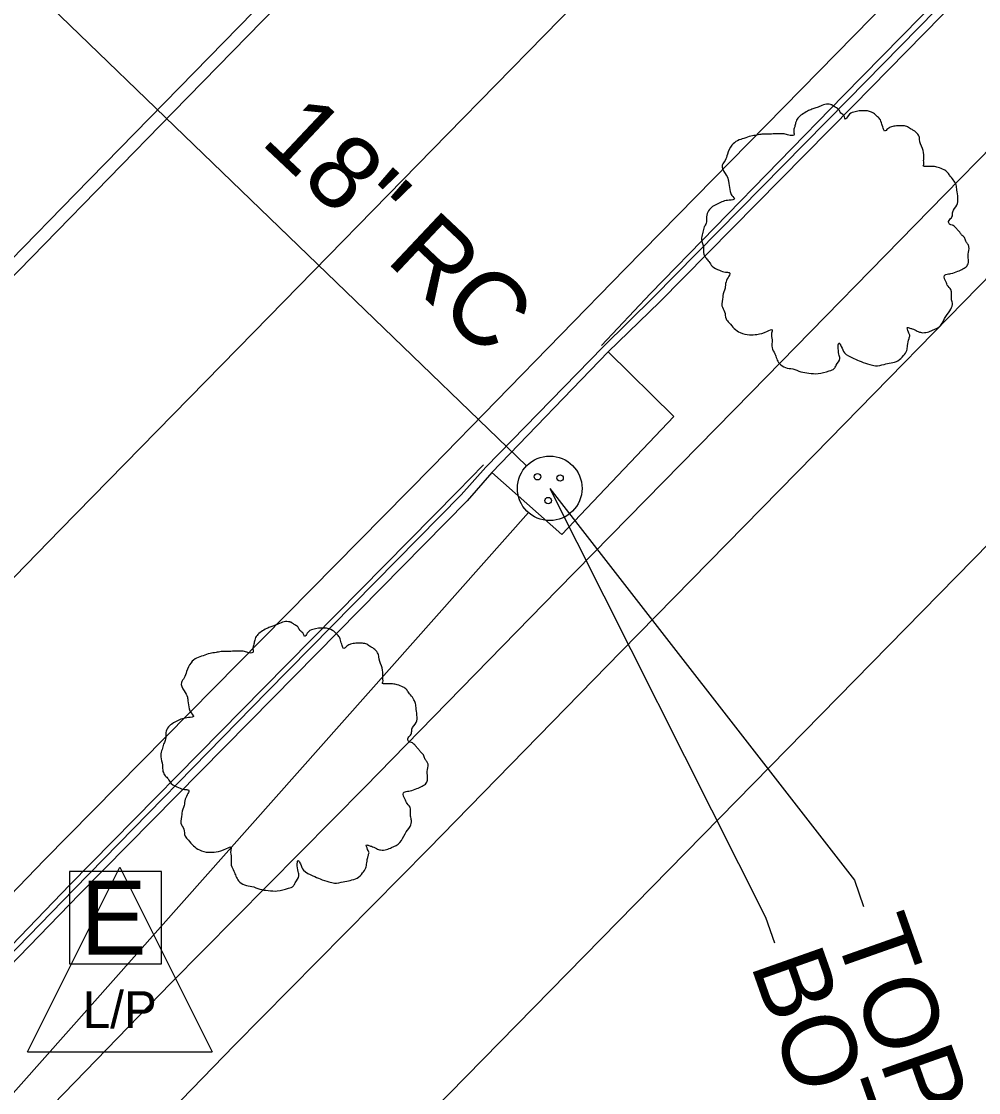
# Model space of a CAD drawing. Extents: x 2004847 to 2009016, y 1134161 to 1140101.
# Drawn here: x 2008246.9 to 2008298.8, y 1139479.2 to 1139537.2 of the extents above; entities that cross this region are included whole.
import ezdxf

# ---------------------------------------------------------------- set-up
doc = ezdxf.new("R2010")
doc.units = 0
for name, color, linetype in [('RD_EX_Conc', 7, 'Continuous'), ('RD_EX_Curb', 7, 'Continuous'), ('RD_EX_DR_Inlet', 7, 'Continuous'), ('RD_EX_DR_Inlet_txCode', 7, 'Continuous'), ('RD_EX_DR_Pipe', 7, 'Continuous'), ('RD_EX_DR_Pipe_txCode', 7, 'Continuous'), ('RD_EX_Pavement_Markings', 7, 'Continuous'), ('RD_EX_Road', 7, 'Continuous'), ('RD_EX_SU_Elec', 7, 'Continuous'), ('RD_EX_UT', 7, 'Continuous'), ('RD_EX_VEG', 7, 'Continuous')]:
    doc.layers.add(name, color=color, linetype=linetype)

msp = doc.modelspace()

# ---------------------------------------------------------------- linework, layer by layer
at = {"layer": 'RD_EX_Conc'}
for points in [[(2008321.411, 1139545.804), (2008310.877, 1139535.196), (2008300.368, 1139524.489), (2008289.885, 1139513.771), (2008279.393, 1139503.086), (2008268.931, 1139492.374), (2008258.431, 1139481.764), (2008248.004, 1139471.024), (2008237.636, 1139460.225), (2008227.509, 1139449.571), (2008217.402, 1139438.786), (2008207.395, 1139427.906), (2008202.961, 1139423.051), (2008201.333, 1139421.68), (2008198.959, 1139420.07), (2008190.968, 1139414.867), (2008184.164, 1139410.721), (2008181.158, 1139407.25), (2008177.744, 1139401.91), (2008173.509, 1139394.642), (2008169.621, 1139389.646)], [(2008307.425, 1139538.568), (2008296.932, 1139527.849), (2008286.451, 1139517.133), (2008275.958, 1139506.447), (2008265.496, 1139495.734), (2008254.989, 1139485.117), (2008244.551, 1139474.384), (2008234.182, 1139463.585), (2008224.01, 1139452.902), (2008213.877, 1139442.09), (2008203.845, 1139431.182), (2008199.336, 1139426.21), (2008198.333, 1139425.289), (2008196.183, 1139423.915), (2008188.705, 1139419.127), (2008180.391, 1139413.694), (2008176.664, 1139409.868)]]:
    msp.add_lwpolyline(points, dxfattribs=at)
at = {"layer": 'RD_EX_Curb'}
for points in [[(2008396.425, 1139640.195), (2008385.814, 1139629.396), (2008375.41, 1139618.786), (2008364.915, 1139608.033), (2008354.502, 1139597.264), (2008344.083, 1139586.553), (2008333.641, 1139575.853), (2008323.094, 1139565.135), (2008312.626, 1139554.408), (2008302.175, 1139543.696), (2008291.683, 1139532.985), (2008281.159, 1139522.314), (2008278.416, 1139519.598), (2008272.069, 1139513.083), (2008270.715, 1139511.579), (2008260.203, 1139500.913), (2008249.751, 1139490.22), (2008239.302, 1139479.493), (2008228.934, 1139468.687), (2008218.719, 1139457.937), (2008208.51, 1139447.12), (2008198.436, 1139436.174), (2008197.313, 1139434.932)], [(2008396.24, 1139640.444), (2008385.631, 1139629.577), (2008375.221, 1139618.97), (2008364.727, 1139608.217), (2008354.247, 1139597.515), (2008343.835, 1139586.796), (2008333.392, 1139576.095), (2008322.846, 1139565.378), (2008312.391, 1139554.639), (2008301.947, 1139543.919), (2008291.439, 1139533.224), (2008280.987, 1139522.482), (2008278.336, 1139519.676)], [(2008396.691, 1139640.008), (2008386.119, 1139629.092), (2008375.718, 1139618.485), (2008365.222, 1139607.731), (2008354.782, 1139596.989), (2008344.371, 1139586.272), (2008333.901, 1139575.599), (2008323.354, 1139564.881), (2008312.934, 1139554.107), (2008302.491, 1139543.387), (2008291.999, 1139532.676), (2008281.467, 1139522.013), (2008278.7, 1139519.323), (2008272.39, 1139512.798), (2008271.051, 1139511.25), (2008260.538, 1139500.584), (2008250.031, 1139489.947), (2008239.603, 1139479.2), (2008229.235, 1139468.395), (2008219.023, 1139457.648), (2008208.816, 1139446.833), (2008198.745, 1139435.89), (2008197.609, 1139434.659)], [(2008271.938, 1139513.199), (2008270.519, 1139511.77), (2008260.007, 1139501.104), (2008249.514, 1139490.45), (2008239.118, 1139479.672), (2008228.75, 1139468.867), (2008218.532, 1139458.115), (2008208.322, 1139447.296), (2008198.247, 1139436.349), (2008197.103, 1139435.126)]]:
    msp.add_lwpolyline(points, dxfattribs=at)
at = {"layer": 'RD_EX_DR_Inlet'}
msp.add_lwpolyline([(2008272.39, 1139512.798), (2008276.18, 1139509.435), (2008282.251, 1139515.821), (2008278.7, 1139519.323)], dxfattribs=at)
for centre, radius in [((2008275.524, 1139511.933), 1.75), ((2008274.859, 1139512.563), 0.175), ((2008276.084, 1139512.493), 0.175), ((2008275.437, 1139511.268), 0.175)]:
    msp.add_circle(centre, radius, dxfattribs=at)
at = {"layer": 'RD_EX_DR_Inlet_txCode'}
for points in [[(2008275.524, 1139511.933), (2008287.221, 1139488.703), (2008287.716, 1139487.299)], [(2008275.524, 1139511.933), (2008292.037, 1139490.7), (2008292.54, 1139489.278)]]:
    msp.add_lwpolyline(points, dxfattribs=at)
at = {"layer": 'RD_EX_DR_Pipe'}
for p, q in [((2008234.589, 1139551.466), (2008274.265, 1139513.149)), ((2008274.365, 1139510.627), (2008086.296, 1139298.729))]:
    msp.add_line(p, q, dxfattribs=at)
at = {"layer": 'RD_EX_Pavement_Markings'}
for points in [[(2008407.363, 1139671.704), (2008385.445, 1139648.988), (2008374.872, 1139638.347), (2008364.394, 1139627.613), (2008353.883, 1139616.913), (2008343.372, 1139606.211), (2008332.891, 1139595.48), (2008322.433, 1139584.727), (2008311.936, 1139574.012), (2008301.44, 1139563.296), (2008290.959, 1139552.566), (2008280.469, 1139541.843), (2008269.976, 1139531.124), (2008259.484, 1139520.404), (2008248.995, 1139509.681), (2008238.528, 1139498.937), (2008228.067, 1139488.187), (2008217.61, 1139477.433), (2008207.268, 1139466.568), (2008197.011, 1139455.623), (2008186.837, 1139444.601)], [(2008333.676, 1139613.684), (2008323.2, 1139602.949), (2008312.733, 1139592.204), (2008302.265, 1139581.461), (2008291.727, 1139570.786), (2008281.225, 1139560.075), (2008270.76, 1139549.329), (2008260.282, 1139538.595), (2008249.798, 1139527.867), (2008239.317, 1139517.137), (2008228.883, 1139506.36), (2008218.427, 1139495.606), (2008207.975, 1139484.847), (2008197.608, 1139474.005), (2008187.296, 1139463.112), (2008175.358, 1139450.343)], [(2008162.04, 1139434.549), (2008172.117, 1139445.66), (2008182.274, 1139456.698), (2008192.485, 1139467.686), (2008202.838, 1139478.54), (2008213.235, 1139489.353), (2008223.684, 1139500.115), (2008234.169, 1139510.841), (2008244.634, 1139521.588), (2008255.116, 1139532.318), (2008265.594, 1139543.051), (2008276.066, 1139553.791), (2008286.542, 1139564.526), (2008297.071, 1139575.21), (2008307.576, 1139585.917), (2008318.051, 1139596.653), (2008328.502, 1139607.414), (2008334.144, 1139613.196)]]:
    msp.add_lwpolyline(points, dxfattribs=at)
at = {"layer": 'RD_EX_Road'}
msp.add_lwpolyline([(2008394.916, 1139641.721), (2008384.306, 1139630.894), (2008373.884, 1139620.275), (2008363.394, 1139609.526), (2008352.914, 1139598.824), (2008342.498, 1139588.101), (2008332.052, 1139577.397), (2008321.512, 1139566.685), (2008311.048, 1139555.954), (2008300.603, 1139545.232), (2008290.111, 1139534.523), (2008279.62, 1139523.821), (2008269.156, 1139513.105), (2008258.643, 1139502.438), (2008248.132, 1139491.797), (2008237.735, 1139481.019), (2008227.366, 1139470.212), (2008217.134, 1139459.445), (2008206.914, 1139448.616), (2008196.829, 1139437.658), (2008195.693, 1139436.427)], dxfattribs=at)
at = {"layer": 'RD_EX_SU_Elec'}
msp.add_lwpolyline([(2008254.483, 1139491.169), (2008249.484, 1139491.169), (2008249.484, 1139486.17), (2008254.483, 1139486.17)], close=True, dxfattribs=at)
at = {"layer": 'RD_EX_UT'}
for p, q in [((2008247.219, 1139481.403), (2008252.219, 1139491.403)), ((2008252.219, 1139491.403), (2008257.219, 1139481.403)), ((2008247.219, 1139481.403), (2008257.219, 1139481.403))]:
    msp.add_line(p, q, dxfattribs=at)
at = {"layer": 'RD_EX_VEG'}
msp.add_lwpolyline([(2008203.453, 1139394.864), (2008204.179, 1139411.342), (2008234.391, 1139443.828), (2008269.155, 1139478.185), (2008304.9, 1139514.624), (2008338.337, 1139548.317), (2008373.674, 1139581.356), (2008403.412, 1139605.514), (2008431.878, 1139620.757), (2008464.924, 1139649.942)], dxfattribs=at)
for points in [[(2008290.826, 1139532.719), (2008290.526, 1139532.744), (2008290.201, 1139532.644), (2008289.952, 1139532.545), (2008289.727, 1139532.47), (2008289.502, 1139532.37), (2008289.202, 1139532.195), (2008288.977, 1139531.995), (2008288.852, 1139531.745), (2008288.802, 1139531.52), (2008288.752, 1139531.245), (2008288.752, 1139531.07), (2008288.627, 1139531.045), (2008288.477, 1139531.07), (2008288.227, 1139531.145), (2008287.977, 1139531.145), (2008287.727, 1139531.145), (2008287.378, 1139531.12), (2008287.028, 1139531.12), (2008286.753, 1139531.07), (2008286.428, 1139531.02), (2008286.053, 1139530.895), (2008285.703, 1139530.77), (2008285.404, 1139530.52), (2008285.154, 1139530.046), (2008285.029, 1139529.696), (2008284.879, 1139529.446), (2008285.029, 1139528.996), (2008285.204, 1139528.646), (2008285.229, 1139528.446), (2008285.304, 1139528.022), (2008285.404, 1139527.797), (2008285.528, 1139527.597), (2008285.454, 1139527.572), (2008285.079, 1139527.522), (2008284.779, 1139527.422), (2008284.354, 1139527.197), (2008284.129, 1139526.972), (2008284.029, 1139526.647), (2008284.004, 1139526.297), (2008283.904, 1139526.097), (2008283.829, 1139525.822), (2008283.804, 1139525.747), (2008283.754, 1139525.423), (2008283.854, 1139524.973), (2008283.879, 1139524.623), (2008284.004, 1139524.398), (2008284.154, 1139524.223), (2008284.329, 1139523.973), (2008284.729, 1139523.748), (2008285.054, 1139523.648), (2008285.254, 1139523.623), (2008285.079, 1139523.124), (2008285.029, 1139522.774), (2008284.904, 1139522.374), (2008284.904, 1139522.299), (2008284.854, 1139521.824), (2008285.004, 1139521.499), (2008285.079, 1139521.125), (2008285.254, 1139520.9), (2008285.528, 1139520.6), (2008285.853, 1139520.375), (2008286.353, 1139520.25), (2008286.753, 1139520.275), (2008287.328, 1139520.45), (2008287.578, 1139520.525), (2008287.553, 1139520.35), (2008287.578, 1139519.975), (2008287.578, 1139519.55), (2008287.727, 1139519.225), (2008287.827, 1139518.95), (2008287.977, 1139518.701), (2008288.302, 1139518.476), (2008288.702, 1139518.401), (2008289.127, 1139518.251), (2008289.577, 1139518.176), (2008290.076, 1139518.151), (2008290.676, 1139518.301), (2008290.951, 1139518.426), (2008291.051, 1139518.601), (2008291.251, 1139518.975), (2008291.201, 1139519.2), (2008291.226, 1139519.8), (2008291.326, 1139519.625), (2008291.501, 1139519.275), (2008292.001, 1139518.975), (2008292.4, 1139518.801), (2008292.875, 1139518.651), (2008293.175, 1139518.576), (2008293.65, 1139518.651), (2008294.025, 1139518.726), (2008294.4, 1139518.851), (2008294.699, 1139519.125), (2008294.874, 1139519.4), (2008294.924, 1139519.675), (2008294.999, 1139520.05), (2008295.049, 1139520.225)], [(2008295.049, 1139520.225), (2008294.974, 1139520.4), (2008294.924, 1139520.65), (2008294.999, 1139520.625), (2008295.174, 1139520.575), (2008295.449, 1139520.45), (2008295.674, 1139520.375), (2008295.999, 1139520.4), (2008296.274, 1139520.5), (2008296.724, 1139520.775), (2008296.998, 1139521.249), (2008297.273, 1139521.649), (2008297.348, 1139521.974), (2008297.298, 1139522.199), (2008297.273, 1139522.699), (2008297.073, 1139522.949), (2008297.023, 1139523.074), (2008296.923, 1139523.473), (2008296.998, 1139523.523), (2008297.273, 1139523.573), (2008297.648, 1139523.698), (2008297.923, 1139523.823), (2008298.148, 1139523.998), (2008298.223, 1139524.223), (2008298.198, 1139524.623), (2008298.248, 1139525.023), (2008298.173, 1139525.173), (2008298.073, 1139525.323), (2008297.998, 1139525.523), (2008297.848, 1139525.672), (2008297.748, 1139525.822), (2008297.648, 1139525.922), (2008297.523, 1139526.072), (2008297.348, 1139526.197), (2008297.198, 1139526.247), (2008297.148, 1139526.397), (2008297.298, 1139526.597), (2008297.348, 1139526.697), (2008297.373, 1139526.922), (2008297.598, 1139527.272), (2008297.648, 1139527.672), (2008297.598, 1139528.096), (2008297.548, 1139528.371), (2008297.398, 1139528.646), (2008297.198, 1139528.896), (2008297.073, 1139529.071), (2008296.898, 1139529.196), (2008296.574, 1139529.321), (2008296.324, 1139529.371), (2008295.974, 1139529.371), (2008295.774, 1139529.421), (2008295.799, 1139529.471), (2008295.799, 1139529.621), (2008295.799, 1139529.896), (2008295.724, 1139530.345), (2008295.574, 1139530.845), (2008295.574, 1139530.87), (2008295.474, 1139531.12), (2008295.249, 1139531.32), (2008295.074, 1139531.42), (2008294.874, 1139531.545), (2008294.624, 1139531.57), (2008294.325, 1139531.57), (2008294.05, 1139531.52), (2008293.85, 1139531.42), (2008293.675, 1139531.295), (2008293.6, 1139531.445), (2008293.5, 1139531.745), (2008293.45, 1139531.895), (2008293.3, 1139532.07), (2008293.075, 1139532.27), (2008292.625, 1139532.395), (2008292.001, 1139532.32), (2008291.701, 1139532.12), (2008291.551, 1139531.945), (2008291.501, 1139532.07), (2008291.301, 1139532.27), (2008291.201, 1139532.445), (2008291.026, 1139532.57), (2008290.876, 1139532.669), (2008290.776, 1139532.719)], [(2008261.507, 1139504.686), (2008261.207, 1139504.711), (2008260.882, 1139504.611), (2008260.633, 1139504.511), (2008260.408, 1139504.436), (2008260.183, 1139504.336), (2008259.883, 1139504.161), (2008259.658, 1139503.961), (2008259.533, 1139503.711), (2008259.483, 1139503.486), (2008259.433, 1139503.211), (2008259.433, 1139503.036), (2008259.308, 1139503.011), (2008259.158, 1139503.036), (2008258.908, 1139503.111), (2008258.658, 1139503.111), (2008258.408, 1139503.111), (2008258.059, 1139503.086), (2008257.709, 1139503.086), (2008257.434, 1139503.036), (2008257.109, 1139502.987), (2008256.734, 1139502.862), (2008256.384, 1139502.737), (2008256.085, 1139502.487), (2008255.835, 1139502.012), (2008255.71, 1139501.662), (2008255.56, 1139501.412), (2008255.71, 1139500.962), (2008255.885, 1139500.613), (2008255.91, 1139500.413), (2008255.985, 1139499.988), (2008256.085, 1139499.763), (2008256.209, 1139499.563), (2008256.135, 1139499.538), (2008255.76, 1139499.488), (2008255.46, 1139499.388), (2008255.035, 1139499.163), (2008254.81, 1139498.938), (2008254.71, 1139498.613), (2008254.685, 1139498.264), (2008254.585, 1139498.064), (2008254.51, 1139497.789), (2008254.485, 1139497.714), (2008254.435, 1139497.389), (2008254.535, 1139496.939), (2008254.56, 1139496.589), (2008254.685, 1139496.364), (2008254.835, 1139496.19), (2008255.01, 1139495.94), (2008255.41, 1139495.715), (2008255.735, 1139495.615), (2008255.935, 1139495.59), (2008255.76, 1139495.09), (2008255.71, 1139494.74), (2008255.585, 1139494.34), (2008255.585, 1139494.265), (2008255.535, 1139493.791), (2008255.685, 1139493.466), (2008255.76, 1139493.091), (2008255.935, 1139492.866), (2008256.209, 1139492.566), (2008256.534, 1139492.341), (2008257.034, 1139492.216), (2008257.434, 1139492.241), (2008258.009, 1139492.416), (2008258.259, 1139492.491), (2008258.234, 1139492.316), (2008258.259, 1139491.941), (2008258.259, 1139491.517), (2008258.408, 1139491.192), (2008258.508, 1139490.917), (2008258.658, 1139490.667), (2008258.983, 1139490.442), (2008259.383, 1139490.367), (2008259.808, 1139490.217), (2008260.258, 1139490.142), (2008260.757, 1139490.117), (2008261.357, 1139490.267), (2008261.632, 1139490.392), (2008261.732, 1139490.567), (2008261.932, 1139490.942), (2008261.882, 1139491.167), (2008261.907, 1139491.766), (2008262.007, 1139491.591), (2008262.182, 1139491.242), (2008262.682, 1139490.942), (2008263.081, 1139490.767), (2008263.556, 1139490.617), (2008263.856, 1139490.542), (2008264.331, 1139490.617), (2008264.706, 1139490.692), (2008265.081, 1139490.817), (2008265.38, 1139491.092), (2008265.555, 1139491.367), (2008265.605, 1139491.641), (2008265.68, 1139492.016), (2008265.73, 1139492.191)], [(2008265.73, 1139492.191), (2008265.655, 1139492.366), (2008265.605, 1139492.616), (2008265.68, 1139492.591), (2008265.855, 1139492.541), (2008266.13, 1139492.416), (2008266.355, 1139492.341), (2008266.68, 1139492.366), (2008266.955, 1139492.466), (2008267.405, 1139492.741), (2008267.679, 1139493.216), (2008267.954, 1139493.616), (2008268.029, 1139493.94), (2008267.979, 1139494.165), (2008267.954, 1139494.665), (2008267.754, 1139494.915), (2008267.704, 1139495.04), (2008267.604, 1139495.44), (2008267.679, 1139495.49), (2008267.954, 1139495.54), (2008268.329, 1139495.665), (2008268.604, 1139495.79), (2008268.829, 1139495.965), (2008268.904, 1139496.19), (2008268.879, 1139496.589), (2008268.929, 1139496.989), (2008268.854, 1139497.139), (2008268.754, 1139497.289), (2008268.679, 1139497.489), (2008268.529, 1139497.639), (2008268.429, 1139497.789), (2008268.329, 1139497.889), (2008268.204, 1139498.039), (2008268.029, 1139498.164), (2008267.879, 1139498.214), (2008267.829, 1139498.364), (2008267.979, 1139498.563), (2008268.029, 1139498.663), (2008268.054, 1139498.888), (2008268.279, 1139499.238), (2008268.329, 1139499.638), (2008268.279, 1139500.063), (2008268.229, 1139500.338), (2008268.079, 1139500.613), (2008267.879, 1139500.862), (2008267.754, 1139501.037), (2008267.579, 1139501.162), (2008267.255, 1139501.287), (2008267.005, 1139501.337), (2008266.655, 1139501.337), (2008266.455, 1139501.387), (2008266.48, 1139501.437), (2008266.48, 1139501.587), (2008266.48, 1139501.862), (2008266.405, 1139502.312), (2008266.255, 1139502.812), (2008266.255, 1139502.837), (2008266.155, 1139503.086), (2008265.93, 1139503.286), (2008265.755, 1139503.386), (2008265.555, 1139503.511), (2008265.305, 1139503.536), (2008265.006, 1139503.536), (2008264.731, 1139503.486), (2008264.531, 1139503.386), (2008264.356, 1139503.261), (2008264.281, 1139503.411), (2008264.181, 1139503.711), (2008264.131, 1139503.861), (2008263.981, 1139504.036), (2008263.756, 1139504.236), (2008263.306, 1139504.361), (2008262.682, 1139504.286), (2008262.382, 1139504.086), (2008262.232, 1139503.911), (2008262.182, 1139504.036), (2008261.982, 1139504.236), (2008261.882, 1139504.411), (2008261.707, 1139504.536), (2008261.557, 1139504.636), (2008261.457, 1139504.686)]]:
    msp.add_spline(points, degree=3, dxfattribs=at)

# ---------------------------------------------------------------- texts
at = {"layer": 'RD_EX_DR_Inlet_txCode'}
for s, p in [("TOP=574.98'", (2008290.914, 1139487.885)), ("BOTTOM OF BOX = 570.78'", (2008286.39, 1139486.132))]:
    msp.add_text(s, height=4.00001, rotation=289.44941, dxfattribs=at).set_placement(p)
at = {"layer": 'RD_EX_DR_Pipe_txCode'}
msp.add_text('18" RC', height=4, rotation=316.6976, dxfattribs=at).set_placement((2008259.788, 1139530.663))
at = {"layer": 'RD_EX_SU_Elec'}
msp.add_text('E', height=4, dxfattribs=at).set_placement((2008250.097, 1139486.67))
at = {"layer": 'RD_EX_UT'}
msp.add_text('L/P', height=2, dxfattribs=at).set_placement((2008250.211, 1139482.684))

doc.saveas('drawing.dxf')
